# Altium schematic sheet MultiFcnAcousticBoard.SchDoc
size A3
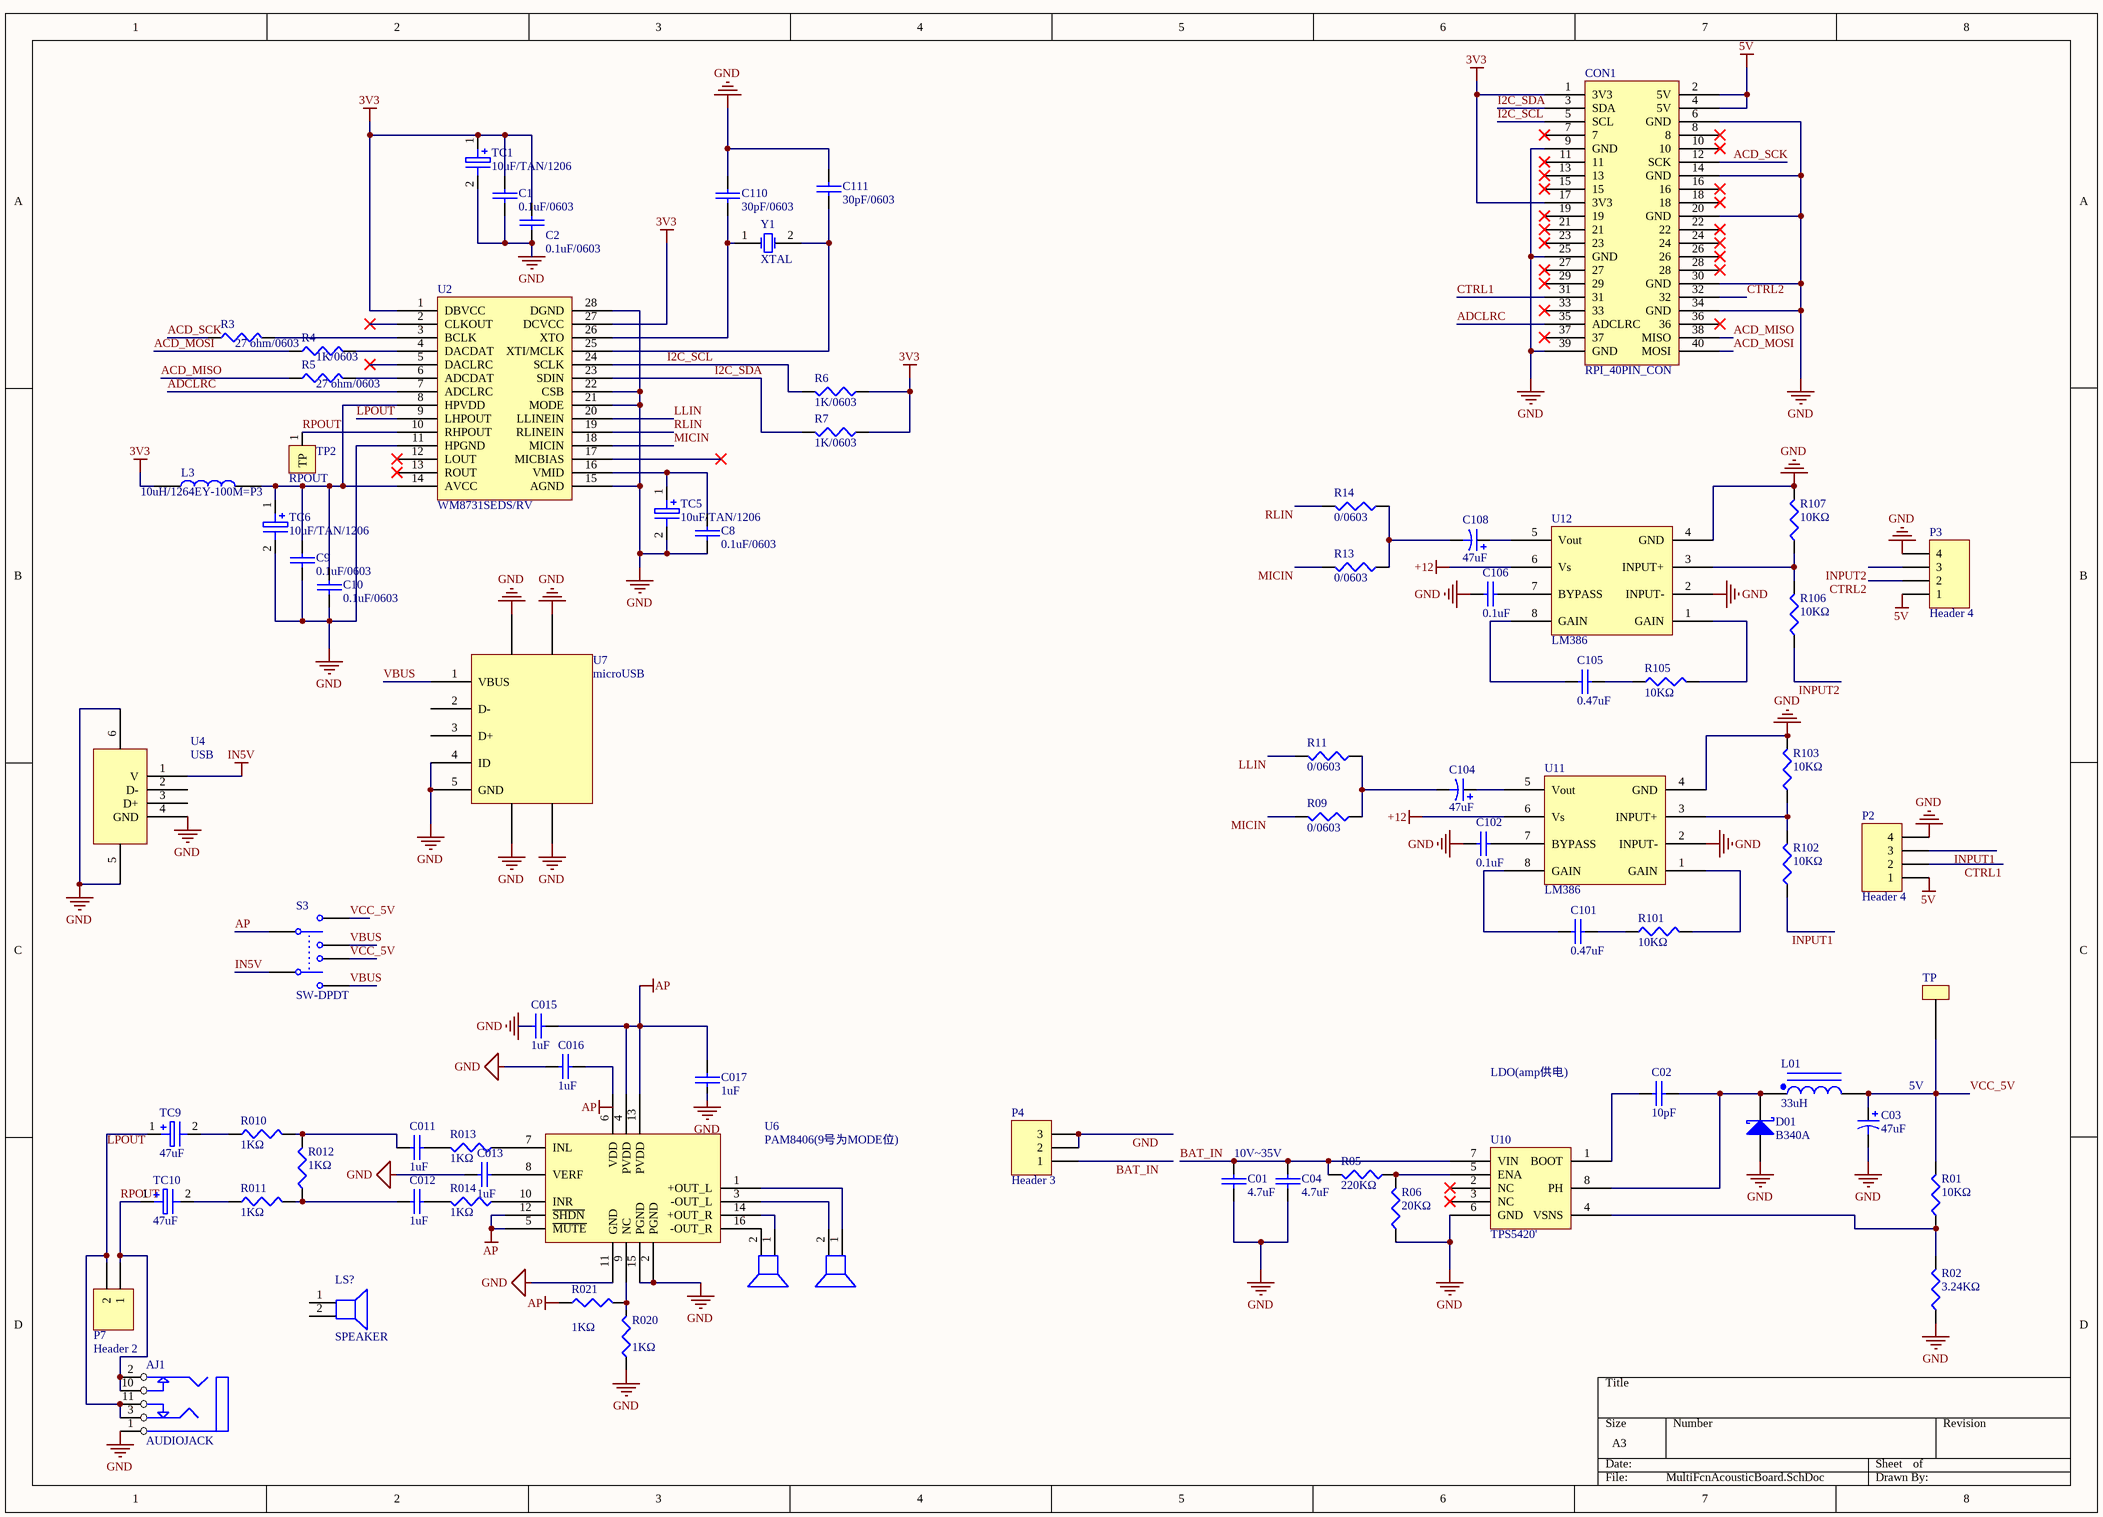
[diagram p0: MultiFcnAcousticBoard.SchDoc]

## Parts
AJ1  AUDIOJACK  [PJ-325C]
C1  0.1uF/0603  [C0603]
C01  4.7uF  [C0603]
C2  0.1uF/0603  [C0603]
C02  10pF  [C0603]
C03  47uF  [TAN A]
C04  4.7uF  [C0603]
C8  0.1uF/0603  [C0603]
C9  0.1uF/0603  [C0603]
C10  0.1uF/0603  [C0603]
C011  1uF  [C0603]
C012  1uF  [C0603]
C013  1uF  [C0603]
C015  1uF  [C0603]
C016  1uF  [C0603]
C017  1uF  [C0603]
C101  0.47uF  [C0603]
C102  0.1uF  [C0603]
C104  47uF  [TAN A]
C105  0.47uF  [C0603]
C106  0.1uF  [C0603]
C108  47uF  [TAN A]
C110  30pF/0603  [C0603]
C111  30pF/0603  [C0603]
CON1  RPI_40PIN_CON  [HDR2X20]
D01  B340A  [DIODE-SMA]
L01  33uH  [INDUCTOR]
L3  10uH/1264EY-100M=P3  [INDUCTOR]
LS?  SPEAKER  [SPEAKER]
P2  Header 4  [HDR1X4]
P3  Header 4  [HDR1X4]
P4  Header 3  [DC-005]
P7  Header 2  [HDR1X2]
R01  10KΩ  [R0603]
R02  3.24KΩ  [R0603]
R3  27 ohm/0603  [R0603]
R4  1K/0603  [R0603]
R5  27 ohm/0603  [R0603]
R05  220KΩ  [R0603]
R6  1K/0603  [R0603]
R06  20KΩ  [R0603]
R7  1K/0603  [R0603]
R09  0/0603  [R0603]
R010  1KΩ  [R0603]
R11  0/0603  [R0603]
R011  1KΩ  [R0603]
R012  1KΩ  [R0603]
R013  1KΩ  [R0603]
R13  0/0603  [R0603]
R014  1KΩ  [R0603]
R14  0/0603  [R0603]
R020  value 1KΩ  [R0603]
R021  value 1KΩ  [R0603]
R101  10KΩ  [R0603]
R102  10KΩ  [R0603]
R103  10KΩ  [R0603]
R105  10KΩ  [R0603]
R106  10KΩ  [R0603]
R107  10KΩ  [R0603]
S3  SW-DPDT  [DPDT-6]
SPEAKER  (no value)  [HDR1X2]
SPEAKER1  (no value)  [HDR1X2]
TC1  10uF/TAN/1206  [TAN_A]
TC5  10uF/TAN/1206  [TAN_A]
TC6  10uF/TAN/1206  [TAN_CAP]
TC9  47uF  [TAN_A]
TC10  47uF  [TAN_A]
TP  TESTPOINT  [TP]  (value not drawn)
TP2  RPOUT  [TP]
U2  WM8731SEDS/RV  [SSOP-28_208MIL]
U4  USB  [USB_A1]
U6  PAM8406(9号为MODE位)  [SOIC-16_150MIL]
U7  microUSB  [MICRO-USB-A18]
U10  TPS5420'  [SOIC-8]
U11  LM386  [SOIC-8]
U12  LM386  [SOIC-8]
Y1  XTAL  [R38]

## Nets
3V3: C1.1 C2.1 CON1.1(3V3) CON1.17(3V3) L3.1 R6.1 R7.1 TC1.1 U2.1(DBVCC) U2.27(DCVCC)
5V: CON1.2(5V) CON1.4(5V) P2.1 P3.1
+12: U11.6(Vs) U12.6(Vs)
AP: C015.2 C017.1 R021.1 S3.2 U6.4(PVDD) U6.5(~{MUTE}) U6.12(~{SHDN}) U6.13(PVDD)
GND: AJ1.1 C01.1 C1.2 C2.2 C03.2 C04.1 C8.2 C9.2 C10.2 C013.1 C015.1 C016.1 C017.2 C102.2 C106.2 C110.1 C111.1 CON1.6(GND) CON1.9(GND) CON1.14(GND) CON1.20(GND) CON1.25(GND) CON1.30(GND) CON1.34(GND) CON1.39(GND) D01.3(A) P2.4 P3.4 P4.2 P4.3 R02.1 R06.1 R020.1 R103.2 R107.2 TC1.2(E) TC5.2(E) TC6.2(E) U2.11(HPGND) U2.15(AGND) U2.21(MODE) U2.22(CSB) U2.28(DGND) U4.4(GND) U4.5 U4.6 U6.2(PGND) U6.11(GND) U6.15(PGND) U7.4(ID) U7.5(GND) U7.7 U7.?1 U7.?2 U7.?3 U10.6(GND) U11.2(INPUT-) U11.4(GND) U12.2(INPUT-) U12.4(GND)
IN5V: S3.5 U4.1(V)
ACD_MISO: CON1.38(MISO) R5.1
ACD_MOSI: CON1.40(MOSI) R4.1
ACD_SCK: CON1.12(SCK) R3.1
ADCLRC: CON1.35(ADCLRC) U2.7(ADCLRC)
BAT_IN: C01.2 C04.2 P4.1 R05.2 U10.7(VIN)
CTRL1: CON1.31 P2.2
CTRL2: CON1.32 P3.2
I2C_SCL: CON1.5(SCL) R6.2 U2.24(SCLK)
I2C_SDA: CON1.3(SDA) R7.2 U2.23(SDIN)
INPUT1: P2.3 R102.1
INPUT2: P3.3 R106.1
LLIN: R11.2 U2.20(LLINEIN)
LPOUT: AJ1.3 AJ1.11 P7.2 TC9.1 U2.9(LHPOUT)
MICIN: R09.2 R13.2 U2.18(MICIN)
RLIN: R14.2 U2.19(RLINEIN)
RPOUT: AJ1.2 AJ1.10 P7.1 TC10.1 TP2.1(TP) U2.10(RHPOUT)
VBUS: S3.3 S3.4 U7.1(VBUS)
VCC_5V: C03.1 L01.2 R01.2 S3.1 S3.6 TP.?1
NetC02_1: C02.1 U10.1(BOOT)
NetC02_2: C02.2 D01.1(K) L01.1 U10.8(PH)
NetC8_1: C8.1 TC5.1 U2.16(VMID)
NetC9_1: C9.1 C10.1 L3.2 TC6.1 U2.8(HPVDD) U2.14(AVCC)
NetC011_1: C011.1 R010.2 R012.2
NetC011_2: C011.2 R013.2
NetC012_1: C012.1 R011.2 R012.1
NetC012_2: C012.2 R014.2
NetC013_2: C013.2 U6.8(VERF)
NetC016_2: C016.2 U6.6(VDD)
NetC101_1: C101.1 R101.1
NetC101_2: C101.2 U11.8(GAIN)
NetC102_1: C102.1 U11.7(BYPASS)
NetC104_1: C104.1 U11.5(Vout)
NetC104_2: C104.2 R09.1 R11.1
NetC105_1: C105.1 R105.1
NetC105_2: C105.2 U12.8(GAIN)
NetC106_1: C106.1 U12.7(BYPASS)
NetC108_1: C108.1 U12.5(Vout)
NetC108_2: C108.2 R13.1 R14.1
NetC110_2: C110.2 U2.26(XTO) Y1.1(OSC1)
NetC111_2: C111.2 U2.25(XTI/MCLK) Y1.2(OSC2)
NetR01_1: R01.1 R02.2 U10.4(VSNS)
NetR3_2: R3.2 U2.3(BCLK)
NetR4_2: R4.2 U2.4(DACDAT)
NetR05_1: R05.1 R06.2 U10.5(ENA)
NetR5_2: R5.2 U2.6(ADCDAT)
NetR010_1: R010.1 TC9.2(E)
NetR011_1: R011.1 TC10.2(E)
NetR013_1: R013.1 U6.7(INL)
NetR014_1: R014.1 U6.10(INR)
NetR020_2: R020.2 R021.2 U6.9(NC)
NetR101_2: R101.2 U11.1(GAIN)
NetR102_2: R102.2 R103.1 U11.3(INPUT+)
NetR105_2: R105.2 U12.1(GAIN)
NetR106_2: R106.2 R107.1 U12.3(INPUT+)
NetSPEAKER1_1: SPEAKER1.1 U6.1(+OUT_L)
NetSPEAKER1_2: SPEAKER1.2 U6.3(-OUT_L)
NetSPEAKER_1: SPEAKER.1 U6.14(+OUT_R)
NetSPEAKER_2: SPEAKER.2 U6.16(-OUT_R)

Not connected (* = marked no-connect by the designer): CON1 7* 8* 10* 11* 13* 15* 16* 18* 19* 21* 22* 23* 24* 26* 27* 28* 29* 33* 36* 37*; LS? 1 2; U2 2(CLKOUT)* 5(DACLRC)* 12(LOUT)* 13(ROUT)* 17(MICBIAS)*; U4 2(D-) 3(D+); U7 2(D-) 3(D+); U10 2(NC)* 3(NC)*

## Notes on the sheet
- LDO(amp供电)
- 5V
- 10V~35V
- Labels drawn without touching a wire or pin: AP

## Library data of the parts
C1 C01 C2 C02 C04 C8-C10 C011 C012 C013 C015 C016 C017 C101 C102 C105 C106 C110 C111 = C
C03 C104 C108 = Cap Pol2: Polarized Capacitor (Axial)
D01 = Diode 10TQ040: Schottky Rectifier; Note: Terminal 2 is the TAB and is electrically connected to the cathode
L01 = Inductor Iron Dot: Magnetic-Core Inductor with Winding Polarity Marking
L3 = L
P2 P3 = Header 4: Header, 4-Pin
P4 = Header 3: Header, 3-Pin
P7 = Header 2: Header, 2-Pin
R01 R02-R5 R05 R6 R06 R7 R09 R010 R11 R011 R012 R013 R13 R014 R14 R101-R103 R105-R107 = RES
R020 R021 = Res3: Resistor
S3 = SW-DPDT: Double-Pole, Double-Throw Switch
SPEAKER SPEAKER1 = SPEAKER
TC1 TC5 TC6 TC9 TC10 = TAN_C
TP2 = Testpoint
U2 = XWM8731EDS
U6 = PAM8403
Y1 = XTAL: Crystal Oscillator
